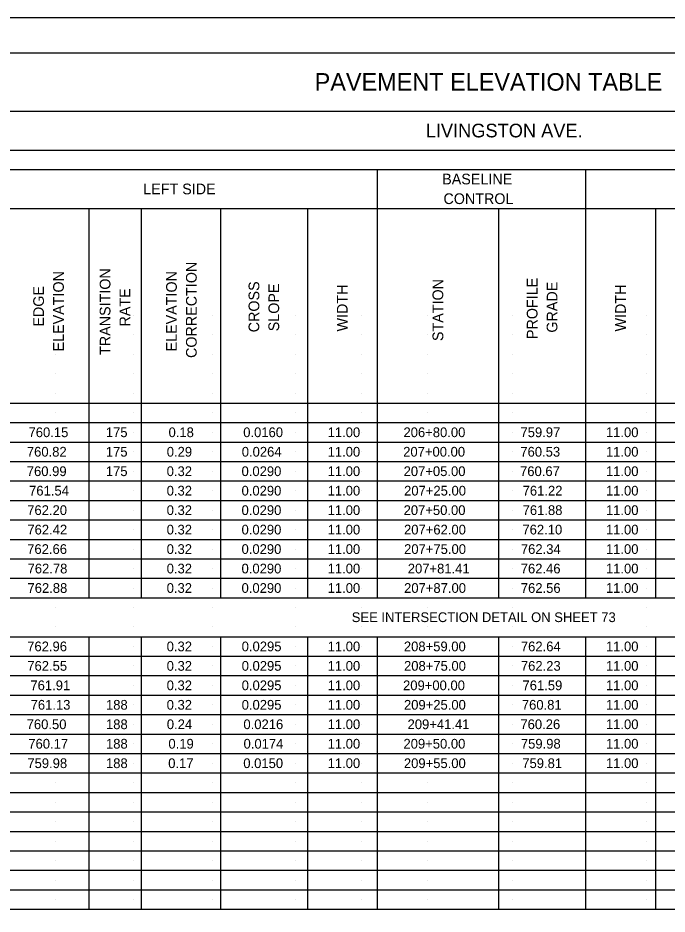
# Model space of a CAD drawing. Extents: x -15.4 to 18.6, y -12.6 to 9.4.
# Drawn here: x -6.22 to 3.11, y -3.5 to 9.39 of the extents above; entities that cross this region are included whole.
import ezdxf

# ---------------------------------------------------------------- set-up
doc = ezdxf.new("R2010")
doc.units = 0
for name, color, linetype in [('SH_Border', 7, 'Continuous'), ('SH_Cut_Line', 7, 'Continuous'), ('SH_Data', 7, 'Continuous'), ('SH_Text', 7, 'Continuous')]:
    doc.layers.add(name, color=color, linetype=linetype)

msp = doc.modelspace()

# ---------------------------------------------------------------- linework, layer by layer
at = {"layer": 'SH_Border'}
msp.add_lwpolyline([(-13.357, 8.888), (18.143, 8.888), (18.143, -12.112), (-13.357, -12.112)], close=True, dxfattribs=at)
at = {"layer": 'SH_Cut_Line'}
msp.add_lwpolyline([(-15.357, -12.612), (18.643, -12.612), (18.643, 9.388), (-15.357, 9.388)], close=True, dxfattribs=at)
at = {"layer": 'SH_Data'}
for p, q in [((-10.905, 8.888), (13.093, 8.888)), ((-9.752, 8.048), (11.215, 8.048)), ((-9.752, 7.488), (11.215, 7.488)), ((-10.905, 7.208), (13.093, 7.208)), ((-1.056, 7.208), (-1.056, 1.048)), ((1.942, 7.208), (1.942, 1.048)), ((-10.905, 6.648), (11.791, 6.648)), ((-5.206, 6.648), (-5.206, 1.048)), ((-4.449, 6.648), (-4.449, 1.048)), ((-3.312, 6.648), (-3.312, 1.048)), ((-2.06, 6.648), (-2.06, 1.048)), ((0.69, 6.648), (0.69, 1.048)), ((2.947, 6.648), (2.947, 1.048)), ((-5.682, 5.108), (-5.682, 5.108)), ((-4.557, 5.108), (-4.557, 5.108)), ((-3.432, 5.108), (-3.432, 5.108)), ((-2.232, 5.108), (-2.232, 5.108)), ((-1.282, 5.108), (-1.282, 5.108)), ((-0.332, 5.108), (-0.332, 5.108)), ((0.893, 5.108), (0.893, 5.108)), ((2.818, 5.108), (2.818, 5.108)), ((-5.682, 4.828), (-5.682, 4.828)), ((-4.557, 4.828), (-4.557, 4.828)), ((-3.432, 4.828), (-3.432, 4.828)), ((-2.232, 4.828), (-2.232, 4.828)), ((-1.282, 4.828), (-1.282, 4.828)), ((-0.332, 4.828), (-0.332, 4.828)), ((0.893, 4.828), (0.893, 4.828)), ((2.818, 4.828), (2.818, 4.828)), ((-5.682, 4.548), (-5.682, 4.548)), ((-4.557, 4.548), (-4.557, 4.548)), ((-3.432, 4.548), (-3.432, 4.548)), ((-2.232, 4.548), (-2.232, 4.548)), ((-1.282, 4.548), (-1.282, 4.548)), ((-0.332, 4.548), (-0.332, 4.548)), ((0.893, 4.548), (0.893, 4.548)), ((2.818, 4.548), (2.818, 4.548)), ((-5.682, 4.268), (-5.682, 4.268)), ((-4.557, 4.268), (-4.557, 4.268)), ((-3.432, 4.268), (-3.432, 4.268)), ((-2.232, 4.268), (-2.232, 4.268)), ((-1.282, 4.268), (-1.282, 4.268)), ((-0.332, 4.268), (-0.332, 4.268)), ((0.893, 4.268), (0.893, 4.268)), ((2.818, 4.268), (2.818, 4.268)), ((-5.682, 3.988), (-5.682, 3.988)), ((-4.557, 3.988), (-4.557, 3.988)), ((-3.432, 3.988), (-3.432, 3.988)), ((-2.232, 3.988), (-2.232, 3.988)), ((-1.282, 3.988), (-1.282, 3.988)), ((-0.332, 3.988), (-0.332, 3.988)), ((0.893, 3.988), (0.893, 3.988)), ((2.818, 3.988), (2.818, 3.988)), ((-10.905, 3.848), (13.093, 3.848)), ((-5.682, 3.708), (-5.682, 3.708)), ((-4.557, 3.708), (-4.557, 3.708)), ((-3.432, 3.708), (-3.432, 3.708)), ((-2.232, 3.708), (-2.232, 3.708)), ((-1.282, 3.708), (-1.282, 3.708)), ((-0.332, 3.708), (-0.332, 3.708)), ((0.893, 3.708), (0.893, 3.708)), ((2.818, 3.708), (2.818, 3.708)), ((-10.905, 3.568), (13.093, 3.568)), ((-5.682, 3.428), (-5.682, 3.428)), ((-4.557, 3.428), (-4.557, 3.428)), ((-3.432, 3.428), (-3.432, 3.428)), ((-2.232, 3.428), (-2.232, 3.428)), ((-1.282, 3.428), (-1.282, 3.428)), ((-0.332, 3.428), (-0.332, 3.428)), ((0.893, 3.428), (0.893, 3.428)), ((2.818, 3.428), (2.818, 3.428)), ((-10.905, 3.288), (13.093, 3.288)), ((-5.682, 3.148), (-5.682, 3.148)), ((-4.557, 3.148), (-4.557, 3.148)), ((-3.432, 3.148), (-3.432, 3.148)), ((-2.232, 3.148), (-2.232, 3.148)), ((-1.282, 3.148), (-1.282, 3.148)), ((-0.332, 3.148), (-0.332, 3.148)), ((0.893, 3.148), (0.893, 3.148)), ((2.818, 3.148), (2.818, 3.148)), ((-10.905, 3.008), (13.093, 3.008)), ((-5.682, 2.868), (-5.682, 2.868)), ((-4.557, 2.868), (-4.557, 2.868)), ((-3.432, 2.868), (-3.432, 2.868)), ((-2.232, 2.868), (-2.232, 2.868)), ((-1.282, 2.868), (-1.282, 2.868)), ((-0.332, 2.868), (-0.332, 2.868)), ((0.893, 2.868), (0.893, 2.868)), ((2.818, 2.868), (2.818, 2.868)), ((-10.905, 2.728), (13.093, 2.728)), ((-5.682, 2.588), (-5.682, 2.588)), ((-4.557, 2.588), (-4.557, 2.588)), ((-3.432, 2.588), (-3.432, 2.588)), ((-2.232, 2.588), (-2.232, 2.588)), ((-1.282, 2.588), (-1.282, 2.588)), ((-0.332, 2.588), (-0.332, 2.588)), ((0.893, 2.588), (0.893, 2.588)), ((2.818, 2.588), (2.818, 2.588)), ((-10.905, 2.448), (13.093, 2.448)), ((-5.682, 2.308), (-5.682, 2.308)), ((-4.557, 2.308), (-4.557, 2.308)), ((-3.432, 2.308), (-3.432, 2.308)), ((-2.232, 2.308), (-2.232, 2.308)), ((-1.282, 2.308), (-1.282, 2.308)), ((-0.332, 2.308), (-0.332, 2.308)), ((0.893, 2.308), (0.893, 2.308)), ((2.818, 2.308), (2.818, 2.308)), ((-10.905, 2.168), (13.093, 2.168)), ((-5.682, 2.028), (-5.682, 2.028)), ((-4.557, 2.028), (-4.557, 2.028)), ((-3.432, 2.028), (-3.432, 2.028)), ((-2.232, 2.028), (-2.232, 2.028)), ((-1.282, 2.028), (-1.282, 2.028)), ((-0.332, 2.028), (-0.332, 2.028)), ((0.893, 2.028), (0.893, 2.028)), ((2.818, 2.028), (2.818, 2.028)), ((-10.905, 1.888), (13.093, 1.888)), ((-5.682, 1.748), (-5.682, 1.748)), ((-5.682, 1.748), (-5.682, 1.748)), ((-4.557, 1.748), (-4.557, 1.748)), ((-3.432, 1.748), (-3.432, 1.748)), ((-2.232, 1.748), (-2.232, 1.748)), ((-1.282, 1.748), (-1.282, 1.748)), ((-0.332, 1.748), (-0.332, 1.748)), ((0.893, 1.748), (0.893, 1.748)), ((2.818, 1.748), (2.818, 1.748)), ((-10.905, 1.608), (13.093, 1.608)), ((-5.682, 1.468), (-5.682, 1.468)), ((-5.682, 1.468), (-5.682, 1.468)), ((-4.557, 1.468), (-4.557, 1.468)), ((-3.432, 1.468), (-3.432, 1.468)), ((-2.232, 1.468), (-2.232, 1.468)), ((-1.282, 1.468), (-1.282, 1.468)), ((-0.332, 1.468), (-0.332, 1.468)), ((0.893, 1.468), (0.893, 1.468)), ((2.818, 1.468), (2.818, 1.468)), ((-10.905, 1.328), (13.093, 1.328)), ((-5.685, 1.188), (-5.685, 1.188)), ((-5.685, 1.188), (-5.685, 1.188)), ((-5.682, 1.188), (-5.682, 1.188)), ((-4.557, 1.188), (-4.557, 1.188)), ((-3.432, 1.188), (-3.432, 1.188)), ((-2.232, 1.188), (-2.232, 1.188)), ((-1.282, 1.188), (-1.282, 1.188)), ((-0.332, 1.188), (-0.332, 1.188)), ((0.893, 1.188), (0.893, 1.188)), ((2.818, 1.188), (2.818, 1.188)), ((-10.905, 1.048), (13.093, 1.048)), ((-5.682, 0.908), (-5.682, 0.908)), ((-4.557, 0.908), (-4.557, 0.908)), ((-3.432, 0.908), (-3.432, 0.908)), ((-2.232, 0.908), (-2.232, 0.908)), ((-1.282, 0.908), (-1.282, 0.908)), ((-0.332, 0.908), (-0.332, 0.908)), ((0.893, 0.908), (0.893, 0.908)), ((2.818, 0.908), (2.818, 0.908)), ((-5.682, 0.628), (-5.682, 0.628)), ((-4.557, 0.628), (-4.557, 0.628)), ((-3.432, 0.628), (-3.432, 0.628)), ((-2.232, 0.628), (-2.232, 0.628)), ((-1.282, 0.628), (-1.282, 0.628)), ((-0.332, 0.628), (-0.332, 0.628)), ((0.893, 0.628), (0.893, 0.628)), ((2.818, 0.628), (2.818, 0.628)), ((-10.905, 0.488), (13.093, 0.488)), ((-5.206, 0.488), (-5.206, -3.432)), ((-4.449, 0.488), (-4.449, -3.432)), ((-3.312, 0.488), (-3.312, -3.432)), ((-2.06, 0.488), (-2.06, -3.432)), ((-1.056, 0.488), (-1.056, -3.432)), ((0.69, 0.488), (0.69, -3.432)), ((1.942, 0.488), (1.942, -3.432)), ((2.947, 0.488), (2.947, -3.432)), ((-5.682, 0.348), (-5.682, 0.348)), ((-4.557, 0.348), (-4.557, 0.348)), ((-3.432, 0.348), (-3.432, 0.348)), ((-2.232, 0.348), (-2.232, 0.348)), ((-1.282, 0.348), (-1.282, 0.348)), ((-0.332, 0.348), (-0.332, 0.348)), ((0.893, 0.348), (0.893, 0.348)), ((2.818, 0.348), (2.818, 0.348)), ((-10.905, 0.208), (13.093, 0.208)), ((-5.682, 0.068), (-5.682, 0.068)), ((-4.557, 0.068), (-4.557, 0.068)), ((-3.432, 0.068), (-3.432, 0.068)), ((-2.232, 0.068), (-2.232, 0.068)), ((-1.282, 0.068), (-1.282, 0.068)), ((-0.332, 0.068), (-0.332, 0.068)), ((0.893, 0.068), (0.893, 0.068)), ((2.818, 0.068), (2.818, 0.068)), ((-10.905, -0.072), (13.093, -0.072)), ((-5.682, -0.212), (-5.682, -0.212)), ((-4.557, -0.212), (-4.557, -0.212)), ((-3.432, -0.212), (-3.432, -0.212)), ((-2.232, -0.212), (-2.232, -0.212)), ((-1.282, -0.212), (-1.282, -0.212)), ((-0.332, -0.212), (-0.332, -0.212)), ((0.893, -0.212), (0.893, -0.212)), ((2.818, -0.212), (2.818, -0.212)), ((-10.905, -0.352), (13.093, -0.352)), ((-5.682, -0.492), (-5.682, -0.492)), ((-4.557, -0.492), (-4.557, -0.492)), ((-3.432, -0.492), (-3.432, -0.492)), ((-2.232, -0.492), (-2.232, -0.492)), ((-1.282, -0.492), (-1.282, -0.492)), ((-0.332, -0.492), (-0.332, -0.492)), ((0.893, -0.492), (0.893, -0.492)), ((2.818, -0.492), (2.818, -0.492)), ((-10.905, -0.632), (13.093, -0.632)), ((-5.682, -0.772), (-5.682, -0.772)), ((-4.557, -0.772), (-4.557, -0.772)), ((-3.432, -0.772), (-3.432, -0.772)), ((-2.232, -0.772), (-2.232, -0.772)), ((-1.282, -0.772), (-1.282, -0.772)), ((-0.332, -0.772), (-0.332, -0.772)), ((0.893, -0.772), (0.893, -0.772)), ((2.818, -0.772), (2.818, -0.772)), ((-10.905, -0.912), (13.093, -0.912)), ((-5.682, -1.052), (-5.682, -1.052)), ((-4.557, -1.052), (-4.557, -1.052)), ((-3.432, -1.052), (-3.432, -1.052)), ((-2.232, -1.052), (-2.232, -1.052)), ((-1.282, -1.052), (-1.282, -1.052)), ((-0.332, -1.052), (-0.332, -1.052)), ((0.893, -1.052), (0.893, -1.052)), ((2.818, -1.052), (2.818, -1.052)), ((-10.905, -1.192), (13.093, -1.192)), ((-5.682, -1.332), (-5.682, -1.332)), ((-4.557, -1.332), (-4.557, -1.332)), ((-3.432, -1.332), (-3.432, -1.332)), ((-2.232, -1.332), (-2.232, -1.332)), ((-1.282, -1.332), (-1.282, -1.332)), ((-0.332, -1.332), (-0.332, -1.332)), ((0.893, -1.332), (0.893, -1.332)), ((2.818, -1.332), (2.818, -1.332)), ((-10.905, -1.472), (13.093, -1.472)), ((-5.682, -1.612), (-5.682, -1.612)), ((-4.557, -1.612), (-4.557, -1.612)), ((-3.432, -1.612), (-3.432, -1.612)), ((-2.232, -1.612), (-2.232, -1.612)), ((-1.282, -1.612), (-1.282, -1.612)), ((-0.332, -1.612), (-0.332, -1.612)), ((0.893, -1.612), (0.893, -1.612)), ((2.818, -1.612), (2.818, -1.612)), ((-10.905, -1.752), (13.093, -1.752)), ((-5.682, -1.892), (-5.682, -1.892)), ((-4.557, -1.892), (-4.557, -1.892)), ((-3.432, -1.892), (-3.432, -1.892)), ((-2.232, -1.892), (-2.232, -1.892)), ((-1.282, -1.892), (-1.282, -1.892)), ((-0.332, -1.892), (-0.332, -1.892)), ((0.893, -1.892), (0.893, -1.892)), ((2.818, -1.892), (2.818, -1.892)), ((-10.905, -2.032), (13.093, -2.032)), ((-5.682, -2.172), (-5.682, -2.172)), ((-4.557, -2.172), (-4.557, -2.172)), ((-3.432, -2.172), (-3.432, -2.172)), ((-2.232, -2.172), (-2.232, -2.172)), ((-1.282, -2.172), (-1.282, -2.172)), ((-0.332, -2.172), (-0.332, -2.172)), ((0.893, -2.172), (0.893, -2.172)), ((2.818, -2.172), (2.818, -2.172)), ((-10.905, -2.312), (13.093, -2.312)), ((-5.682, -2.452), (-5.682, -2.452)), ((-4.557, -2.452), (-4.557, -2.452)), ((-3.432, -2.452), (-3.432, -2.452)), ((-2.232, -2.452), (-2.232, -2.452)), ((-1.282, -2.452), (-1.282, -2.452)), ((-0.332, -2.452), (-0.332, -2.452)), ((0.893, -2.452), (0.893, -2.452)), ((2.818, -2.452), (2.818, -2.452)), ((-10.905, -2.592), (13.093, -2.592)), ((-5.682, -2.732), (-5.682, -2.732)), ((-4.557, -2.732), (-4.557, -2.732)), ((-3.432, -2.732), (-3.432, -2.732)), ((-2.232, -2.732), (-2.232, -2.732)), ((-1.282, -2.732), (-1.282, -2.732)), ((-0.332, -2.732), (-0.332, -2.732)), ((0.893, -2.732), (0.893, -2.732)), ((2.818, -2.732), (2.818, -2.732)), ((-10.905, -2.872), (13.093, -2.872)), ((-5.682, -3.012), (-5.682, -3.012)), ((-4.557, -3.012), (-4.557, -3.012)), ((-3.432, -3.012), (-3.432, -3.012)), ((-2.232, -3.012), (-2.232, -3.012)), ((-1.282, -3.012), (-1.282, -3.012)), ((-0.332, -3.012), (-0.332, -3.012)), ((0.893, -3.012), (0.893, -3.012)), ((2.818, -3.012), (2.818, -3.012)), ((-10.905, -3.152), (13.093, -3.152)), ((-5.682, -3.292), (-5.682, -3.292)), ((-4.557, -3.292), (-4.557, -3.292)), ((-3.432, -3.292), (-3.432, -3.292)), ((-2.232, -3.292), (-2.232, -3.292)), ((-1.282, -3.292), (-1.282, -3.292)), ((-0.332, -3.292), (-0.332, -3.292)), ((0.893, -3.292), (0.893, -3.292)), ((2.818, -3.292), (2.818, -3.292)), ((-10.905, -3.432), (13.093, -3.432))]:
    msp.add_line(p, q, dxfattribs=at)

# ---------------------------------------------------------------- texts
at = {"layer": 'SH_Text'}
for s, height, p in [('PAVEMENT ELEVATION TABLE', 0.252, (-1.955, 8.342)), ('LIVINGSTON AVE.', 0.196, (-0.358, 7.67)), ('BASELINE', 0.154, (-0.121, 6.994)), ('LEFT SIDE ', 0.154, (-4.421, 6.851)), ('CONTROL', 0.154, (-0.103, 6.711)), ('760.15', 0.14, (-6.071, 3.358)), ('175', 0.14, (-4.959, 3.358)), ('0.18', 0.14, (-4.057, 3.358)), ('0.0160', 0.14, (-2.983, 3.358)), ('11.00', 0.14, (-1.769, 3.358)), ('206+80.00', 0.14, (-0.678, 3.358)), ('759.97', 0.14, (1.005, 3.358)), ('11.00', 0.14, (2.234, 3.358)), ('760.82', 0.14, (-6.095, 3.078)), ('175', 0.14, (-4.959, 3.078)), ('0.29', 0.14, (-4.083, 3.078)), ('0.0264', 0.14, (-3.004, 3.078)), ('11.00', 0.14, (-1.769, 3.078)), ('207+00.00', 0.14, (-0.682, 3.078)), ('760.53', 0.14, (1.003, 3.078)), ('11.00', 0.14, (2.234, 3.078)), ('760.99', 0.14, (-6.096, 2.798)), ('175', 0.14, (-4.959, 2.798)), ('0.32', 0.14, (-4.084, 2.798)), ('0.0290', 0.14, (-3.007, 2.798)), ('11.00', 0.14, (-1.769, 2.798)), ('207+05.00', 0.14, (-0.676, 2.798)), ('760.67', 0.14, (0.999, 2.798)), ('11.00', 0.14, (2.234, 2.798)), ('761.54', 0.14, (-6.063, 2.518)), ('0.32', 0.14, (-4.084, 2.518)), ('0.0290', 0.14, (-3.007, 2.518)), ('11.00', 0.14, (-1.769, 2.518)), ('207+25.00', 0.14, (-0.669, 2.518)), ('761.22', 0.14, (1.036, 2.518)), ('11.00', 0.14, (2.234, 2.518)), ('762.20', 0.14, (-6.09, 2.238)), ('0.32', 0.14, (-4.084, 2.238)), ('0.0290', 0.14, (-3.007, 2.238)), ('11.00', 0.14, (-1.769, 2.238)), ('207+50.00', 0.14, (-0.676, 2.238)), ('761.88', 0.14, (1.036, 2.238)), ('11.00', 0.14, (2.234, 2.238)), ('762.42', 0.14, (-6.088, 1.958)), ('0.32', 0.14, (-4.084, 1.958)), ('0.0290', 0.14, (-3.007, 1.958)), ('11.00', 0.14, (-1.769, 1.958)), ('207+62.00', 0.14, (-0.67, 1.958)), ('762.10', 0.14, (1.033, 1.958)), ('11.00', 0.14, (2.234, 1.958)), ('762.66', 0.14, (-6.09, 1.678)), ('0.32', 0.14, (-4.084, 1.678)), ('0.0290', 0.14, (-3.007, 1.678)), ('11.00', 0.14, (-1.769, 1.678)), ('207+75.00', 0.14, (-0.669, 1.678)), ('762.34', 0.14, (1.011, 1.678)), ('11.00', 0.14, (2.234, 1.678)), ('762.78', 0.14, (-6.085, 1.398)), ('0.32', 0.14, (-4.084, 1.398)), ('0.0290', 0.14, (-3.007, 1.398)), ('11.00', 0.14, (-1.769, 1.398)), ('207+81.41', 0.14, (-0.616, 1.398)), ('762.46', 0.14, (1.009, 1.398)), ('11.00', 0.14, (2.234, 1.398)), ('762.88', 0.14, (-6.086, 1.118)), ('0.32', 0.14, (-4.084, 1.118)), ('0.0290', 0.14, (-3.007, 1.118)), ('11.00', 0.14, (-1.769, 1.118)), ('207+87.00', 0.14, (-0.669, 1.118)), ('762.56', 0.14, (1.01, 1.118)), ('11.00', 0.14, (2.234, 1.118)), ('SEE INTERSECTION DETAIL ON SHEET 73', 0.14, (-1.422, 0.698)), ('762.96', 0.14, (-6.09, 0.278)), ('0.32', 0.14, (-4.084, 0.278)), ('0.0295', 0.14, (-3.005, 0.278)), ('11.00', 0.14, (-1.769, 0.278)), ('208+59.00', 0.14, (-0.672, 0.278)), ('762.64', 0.14, (1.011, 0.278)), ('11.00', 0.14, (2.234, 0.278)), ('762.55', 0.14, (-6.089, -0.002)), ('0.32', 0.14, (-4.084, -0.002)), ('0.0295', 0.14, (-3.005, -0.002)), ('11.00', 0.14, (-1.769, -0.002)), ('208+75.00', 0.14, (-0.67, -0.002)), ('762.23', 0.14, (1.011, -0.002)), ('11.00', 0.14, (2.234, -0.002)), ('761.91', 0.14, (-6.044, -0.282)), ('0.32', 0.14, (-4.084, -0.282)), ('0.0295', 0.14, (-3.005, -0.282)), ('11.00', 0.14, (-1.769, -0.282)), ('209+00.00', 0.14, (-0.684, -0.282)), ('761.59', 0.14, (1.034, -0.282)), ('11.00', 0.14, (2.234, -0.282)), ('761.13', 0.14, (-6.041, -0.562)), ('188', 0.14, (-4.957, -0.562)), ('0.32', 0.14, (-4.084, -0.562)), ('0.0295', 0.14, (-3.005, -0.562)), ('11.00', 0.14, (-1.769, -0.562)), ('209+25.00', 0.14, (-0.671, -0.562)), ('760.81', 0.14, (1.025, -0.562)), ('11.00', 0.14, (2.234, -0.562)), ('760.50', 0.14, (-6.098, -0.842)), ('188', 0.14, (-4.957, -0.842)), ('0.24', 0.14, (-4.082, -0.842)), ('0.0216', 0.14, (-2.98, -0.842)), ('11.00', 0.14, (-1.769, -0.842)), ('209+41.41', 0.14, (-0.619, -0.842)), ('760.26', 0.14, (1.004, -0.842)), ('11.00', 0.14, (2.234, -0.842)), ('760.17', 0.14, (-6.074, -1.122)), ('188', 0.14, (-4.957, -1.122)), ('0.19', 0.14, (-4.059, -1.122)), ('0.0174', 0.14, (-2.978, -1.122)), ('11.00', 0.14, (-1.769, -1.122)), ('209+50.00', 0.14, (-0.678, -1.122)), ('759.98', 0.14, (1.011, -1.122)), ('11.00', 0.14, (2.234, -1.122)), ('759.98', 0.14, (-6.088, -1.402)), ('188', 0.14, (-4.957, -1.402)), ('0.17', 0.14, (-4.062, -1.402)), ('0.0150', 0.14, (-2.982, -1.402)), ('11.00', 0.14, (-1.769, -1.402)), ('209+55.00', 0.14, (-0.672, -1.402)), ('759.81', 0.14, (1.031, -1.402)), ('11.00', 0.14, (2.234, -1.402))]:
    msp.add_text(s, height=height, dxfattribs=at).set_placement(p)
for s, p in [('CORRECTION', (-3.652, 4.497)), ('ELEVATION', (-5.563, 4.591)), ('TRANSITION', (-4.893, 4.541)), ('ELEVATION', (-3.938, 4.591)), ('CROSS', (-2.752, 4.866)), ('SLOPE', (-2.466, 4.881)), ('STATION', (-0.106, 4.74)), ('PROFILE', (1.25, 4.769)), ('GRADE', (1.536, 4.861)), ('EDGE', (-5.849, 4.948)), ('RATE', (-4.608, 4.95)), ('WIDTH', (-1.481, 4.878)), ('WIDTH', (2.521, 4.878))]:
    msp.add_text(s, height=0.154, rotation=90, dxfattribs=at).set_placement(p)

doc.saveas('drawing.dxf')
